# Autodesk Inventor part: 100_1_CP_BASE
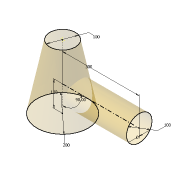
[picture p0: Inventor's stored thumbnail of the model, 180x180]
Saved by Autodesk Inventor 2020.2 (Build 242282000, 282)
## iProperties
Created: 2010-04
Part Number: 100_1_CP_BASE
Document SubType Name: Modeling
Designer: F.Stasiak
Density: 1 g/cm^3
Material: Ogólny
Appearance: Domyślna
Catalog Web Link: www.expertbooks.pl
Manager: www.cadconsulting.pl
Company: Fabian Stasiak CAD Consulting
Średnica_stożka_1: 200,000 mm
Wysokość_stożka: 250,000 mm
Średnica_stożka_2: 100,000 mm
Author: F.Stasiak
Subject: Zbiór ćwiczeń. Autodesk Inventor 2020. Kurs zaawansowany
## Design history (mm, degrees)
sketch "Szkic1"
  geometry: C1 r 100 at (0, 0); 1 further point
  constraints: 1 centre point, 1 coincident
  dimensions: "Średnica_stożka_1" = 200 diameter of C1
node "Płaszczyzna konstrukcyjna1"
sketch "Szkic2"
  geometry: C1 r 50 at (0, 0); 1 further point
  constraints: 1 centre point, 1 coincident
  dimensions: "Średnica_stożka_2" = 100 diameter of C1
sketch "Szkic3"
  geometry: L1 (0, 250)-(0, 0); L2 (0, 100)-(-300, 100)
  constraints: 4 end point, 1 point on line, 1 vertical
  dimensions: "Wysokość_osi_rury" = 100 distance of L2.start L1.end; "Kąt_osi_rury" = 90 deg angle of L2 L1; "Długość_rury_od_osi_stożka" = 300 distance of L2.start L2.end
node "Płaszczyzna konstrukcyjna2"
sketch "Szkic4"
  geometry: C1 r 50 at (0, 0); 1 further point
  constraints: 1 centre point, 1 coincident
  dimensions: "Średnica_rury" = 100 diameter of C1; "Przesunięcie_od_osi_stożka" = 0 distance of point (0, 0) C1.centre
feature "PowWyciągnięciaZłożonego1" dims "d8" = 0, "d9" = 90 deg, "d10" = 0, "d11" = 90 deg
feature "PowWyciągnięciaProstego1" dims "d12" = 10, "d13" = 0
feature "Utnij1"
body "Srf1"
body "Srf2"
other parameters: "Wysokość_stożka" = 250
